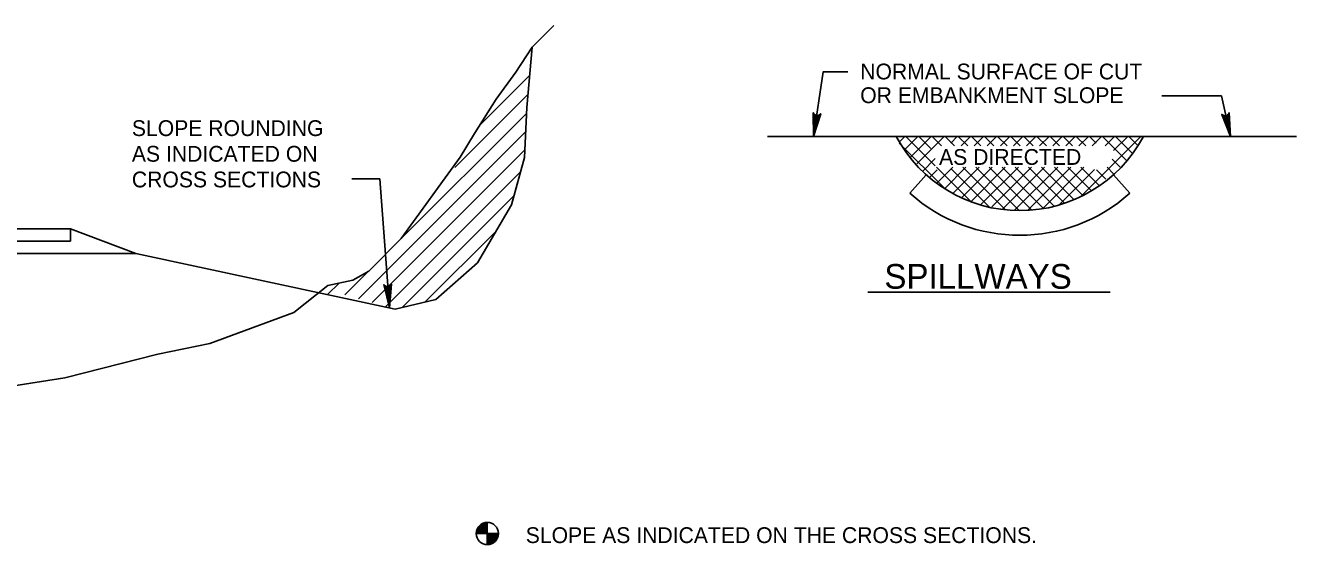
# Model space of a CAD drawing. Extents: x 240 to 1147, y 662 to 1256.
# Drawn here: x 597 to 854.2, y 813.5 to 918.6 of the extents above; entities that cross this region are included whole.
import ezdxf

# ---------------------------------------------------------------- set-up
doc = ezdxf.new("R2010")
doc.units = 0
for name, color, linetype in [('1', 7, 'Continuous'), ('2', 7, 'Continuous'), ('3', 7, 'Continuous')]:
    doc.layers.add(name, color=color, linetype=linetype)

msp = doc.modelspace()

# ---------------------------------------------------------------- linework, layer by layer
at = {"layer": '1'}
for points in [[(757.676, 900.521125), (757.326, 900.402375), (756.44075, 896.112875), (757.676, 900.521125), (757.90725, 900.721125), (756.44075, 896.112875), (756.872, 900.464875), (756.574, 900.671125), (756.44075, 896.112875), (756.397, 900.946125), (756.574, 900.671125)], [(840.36975, 900.666875), (840.0885, 900.429375), (840.822, 896.112875), (840.36975, 900.666875), (840.5135, 900.939875), (840.822, 896.112875), (839.64275, 900.325375), (839.29075, 900.408625), (840.822, 896.112875), (839.024, 900.600375), (839.29075, 900.408625)], [(670.88625, 865.995875), (670.5695, 865.802125), (670.655, 861.424875), (670.88625, 865.995875), (671.0675, 866.243625), (670.655, 861.424875), (670.11325, 865.764625), (669.77775, 865.899875), (670.655, 861.424875), (669.5425, 866.129125), (669.77775, 865.899875)]]:
    msp.add_lwpolyline(points, dxfattribs=at)
at = {"layer": '2'}
for p, q in [((688.9945, 898.485375), (699.05275, 908.543625)), ((683.88, 889.835375), (698.7195, 904.674875)), ((826.914, 904.372125), (838.94275, 904.372125)), ((838.94275, 904.372125), (840.822, 896.112875)), ((672.655, 875.074875), (698.43, 900.849875)), ((664.3715, 863.256125), (698.23625, 897.120875)), ((747.1615, 896.112875), (854.1615, 896.112875)), ((773.1845, 896.112875), (823.1845, 896.112875)), ((773.90325, 895.089875), (774.926, 896.112875)), ((774.92825, 893.464875), (777.57825, 896.112875)), ((781.051, 890.191875), (775.12825, 896.112875)), ((775.99275, 891.877375), (780.22825, 896.112875)), ((777.347, 890.579375), (782.88025, 896.112875)), ((780.176, 893.716375), (777.77825, 896.112875)), ((782.3345, 894.210625), (780.43025, 896.112875)), ((784.9865, 894.210625), (783.08225, 896.112875)), ((784.20275, 894.784625), (785.53225, 896.112875)), ((787.6365, 894.210625), (785.7345, 896.112875)), ((786.28025, 894.210625), (788.1845, 896.112875)), ((790.2885, 894.210625), (788.3845, 896.112875)), ((788.93225, 894.210625), (790.8365, 896.112875)), ((792.94075, 894.210625), (791.0365, 896.112875)), ((791.5845, 894.210625), (793.4885, 896.112875)), ((795.59275, 894.210625), (793.6885, 896.112875)), ((794.2365, 894.210625), (796.1385, 896.112875)), ((798.24475, 894.210625), (796.34075, 896.112875)), ((796.8885, 894.210625), (798.79075, 896.112875)), ((800.89475, 894.210625), (798.99275, 896.112875)), ((799.5385, 894.210625), (801.44275, 896.112875)), ((803.547, 894.210625), (801.64475, 896.112875)), ((802.19075, 894.210625), (804.09475, 896.112875)), ((806.199, 894.210625), (804.29475, 896.112875)), ((804.84275, 894.210625), (806.74475, 896.112875)), ((808.851, 894.210625), (806.947, 896.112875)), ((807.49475, 894.210625), (809.397, 896.112875)), ((811.50325, 894.210625), (809.599, 896.112875)), ((810.14475, 894.210625), (812.049, 896.112875)), ((810.651, 884.108625), (822.65525, 896.112875)), ((813.61375, 894.750125), (812.251, 896.112875)), ((812.797, 894.210625), (814.701, 896.112875)), ((819.66975, 891.346125), (814.901, 896.112875)), ((815.449, 894.210625), (817.35325, 896.112875)), ((817.14625, 893.255875), (820.00325, 896.112875)), ((820.9135, 892.754375), (817.55325, 896.112875)), ((820.15325, 896.164875), (821.90325, 894.414875)), ((822.95525, 896.014875), (822.85725, 896.112875)), ((667.13625, 862.485375), (698.04025, 893.389625)), ((782.9365, 885.654375), (773.801, 894.787875)), ((778.48225, 889.064875), (781.051, 891.631625)), ((788.45725, 882.783625), (781.34275, 889.898125)), ((781.451, 886.727375), (784.61975, 889.898125)), ((782.9865, 885.612875), (787.272, 889.898125)), ((784.66775, 884.641875), (789.924, 889.898125)), ((786.497, 883.819125), (792.576, 889.898125)), ((795.1635, 881.379375), (786.64475, 889.898125)), ((788.17825, 882.850375), (795.22825, 889.898125)), ((797.976, 881.219125), (789.297, 889.898125)), ((790.31975, 882.339875), (797.87825, 889.898125)), ((800.572, 881.275375), (791.949, 889.898125)), ((792.53025, 881.898125), (800.53025, 889.898125)), ((802.98225, 881.516875), (794.601, 889.898125)), ((794.6885, 881.404375), (803.18225, 889.898125)), ((797.176, 881.241875), (805.8345, 889.898125)), ((805.1385, 882.010625), (797.25325, 889.898125)), ((799.80525, 881.219125), (808.4845, 889.898125)), ((807.1865, 882.616875), (799.90325, 889.898125)), ((809.0865, 883.366875), (802.55525, 889.898125)), ((802.874, 881.635625), (811.1365, 889.898125)), ((810.87825, 884.227375), (805.20725, 889.898125)), ((812.526, 885.231625), (807.8595, 889.898125)), ((814.2845, 886.125375), (810.5115, 889.898125)), ((817.14075, 888.571125), (815.8135, 889.898125)), ((818.4595, 889.906625), (816.8615, 891.504625)), ((663.047, 887.517625), (668.70425, 887.517625)), ((668.70425, 887.517625), (670.655, 861.424875)), ((669.90075, 861.712375), (697.1715, 888.985375)), ((775.9135, 884.648125), (779.25325, 888.366875)), ((779.947, 887.877375), (781.44775, 889.376625)), ((792.0595, 881.833625), (784.38125, 889.511625)), ((806.09275, 882.202375), (813.312, 889.421625)), ((815.601, 887.460625), (813.71375, 889.346375)), ((820.45725, 884.648125), (817.11775, 888.366875)), ((673.2175, 861.495875), (695.834, 884.112375)), ((529.92775, 877.420875), (606.16525, 877.420875)), ((619.34025, 872.420875), (606.16525, 877.420875)), ((606.16525, 874.920875), (606.16525, 877.420875)), ((677.83625, 862.579125), (692.23625, 876.979125)), ((515.59025, 874.920875), (606.16525, 874.920875)), ((661.607, 864.027125), (666.3695, 868.789625)), ((658.14875, 864.106125), (660.48825, 866.443625)), ((767.4595, 864.596125), (816.46575, 864.596125)), ((690.464, 813.473375), (690.464, 817.963125)), ((690.464, 813.473375), (690.464, 817.963125)), ((690.464, 817.960875), (690.464, 813.471375)), ((690.464, 817.960875), (690.464, 813.471375)), ((692.70775, 815.719375), (688.21825, 815.719375)), ((692.70775, 815.717125), (688.21825, 815.717125)), ((688.22025, 815.719375), (692.71, 815.719375)), ((688.22025, 815.717125), (692.71, 815.717125))]:
    msp.add_line(p, q, dxfattribs=at)
for points in [[(309.96525, 917.420875), (317.46525, 908.670875), (322.46525, 902.420875), (338.71525, 864.920875), (348.71525, 864.920875), (369.96525, 868.670875), (473.71525, 873.045875), (490.59025, 871.795875), (515.59025, 872.420875), (619.34025, 872.420875), (671.84025, 861.170875), (680.06125, 863.102125), (688.48625, 870.558375), (695.33, 882.272875), (697.96125, 891.858375), (698.48825, 901.977125), (699.54025, 914.227125), (703.88625, 918.620875)], [(593.409, 845.443625), (604.9925, 847.274875), (623.81525, 852.033375), (634.31125, 854.231125), (651.32375, 860.456125), (658.20075, 865.947875), (663.2695, 867.045875), (666.52575, 868.877125), (673.0425, 875.468625), (684.98625, 891.945875), (687.882, 896.706125), (692.22575, 903.662375), (696.207, 909.154125), (699.54025, 914.227125)], [(763.401, 909.231625), (758.401, 909.231625), (756.44075, 896.112875)], [(690.45575, 817.842125), (690.16825, 817.825625), (689.9015, 817.756875), (689.65375, 817.677625), (689.3975, 817.552625), (689.15375, 817.398375), (688.9265, 817.206875), (688.7515, 816.990125), (688.5765, 816.723375), (688.46, 816.458875), (688.36825, 816.169375), (688.32875, 815.908875), (688.3245, 815.710875)], [(690.45775, 817.683875), (690.19325, 817.667125), (689.94525, 817.604625), (689.712, 817.529625), (689.4765, 817.415125), (689.2495, 817.269375), (689.04125, 817.094375), (688.88075, 816.896375), (688.71625, 816.646375), (688.61, 816.402625), (688.5245, 816.131875), (688.487, 815.894375), (688.48275, 815.710875)], [(690.45775, 817.523375), (690.21825, 817.508875), (689.989, 817.450625), (689.7725, 817.379625), (689.55375, 817.275625), (689.34325, 817.140125), (689.15575, 816.981875), (689.01, 816.802625), (688.85775, 816.571375), (688.76, 816.346375), (688.68075, 816.096375), (688.6475, 815.881875), (688.64325, 815.710875)], [(690.45775, 817.363125), (690.24325, 817.350625), (690.03275, 817.296375), (689.83275, 817.231875), (689.63275, 817.135875), (689.439, 817.010875), (689.27025, 816.869375), (689.137, 816.706875), (688.9975, 816.494375), (688.90775, 816.292125), (688.835, 816.058875), (688.80575, 815.867125), (688.8015, 815.710875)], [(690.45775, 817.204625), (690.26825, 817.192125), (690.07875, 817.144375), (689.89125, 817.083875), (689.71, 816.996375), (689.53275, 816.883875), (689.38275, 816.756875), (689.26625, 816.613125), (689.139, 816.417125), (689.05775, 816.233875), (688.99125, 816.023375), (688.96625, 815.852625), (688.962, 815.710875)], [(690.45775, 817.044375), (690.29325, 817.033875), (690.1225, 816.990125), (689.9515, 816.935875), (689.789, 816.856875), (689.62875, 816.754625), (689.4975, 816.644375), (689.39525, 816.519375), (689.27875, 816.340125), (689.20775, 816.177625), (689.1475, 815.985875), (689.1245, 815.840125), (689.12025, 815.710875)], [(690.45775, 816.883875), (690.31825, 816.875625), (690.16625, 816.838125), (690.01, 816.788125), (689.86625, 816.717125), (689.7225, 816.625625), (689.612, 816.531875), (689.5245, 816.425625), (689.42025, 816.265125), (689.35575, 816.123375), (689.30375, 815.950625), (689.28275, 815.825625), (689.28075, 815.710875)], [(690.45775, 816.725625), (690.34125, 816.717125), (690.21, 816.683875), (690.07025, 816.638125), (689.94325, 816.577625), (689.81825, 816.496375), (689.7265, 816.419375), (689.65375, 816.329625), (689.56, 816.188125), (689.50575, 816.067125), (689.45775, 815.915125), (689.44325, 815.810875), (689.44125, 815.710875)], [(690.45775, 816.565125), (690.36625, 816.558875), (690.25375, 816.529625), (690.13075, 816.490125), (690.0225, 816.438125), (689.912, 816.367125), (689.84125, 816.308875), (689.78075, 816.235875), (689.6995, 816.113125), (689.65575, 816.010875), (689.614, 815.877625), (689.6015, 815.796375), (689.5995, 815.710875)], [(690.45775, 816.404625), (690.39125, 816.400625), (690.2995, 816.377625), (690.189, 816.342125), (690.0995, 816.298375), (690.00575, 816.240125), (689.95575, 816.196375), (689.91, 816.142125), (689.84125, 816.035875), (689.80575, 815.954625), (689.77025, 815.842125), (689.762, 815.783875), (689.76, 815.710875)], [(690.45775, 816.246375), (690.41625, 816.242125), (690.34325, 816.223375), (690.2495, 816.194375), (690.17875, 816.158875), (690.1015, 816.110875), (690.06825, 816.083875), (690.039, 816.046375), (689.98075, 815.958875), (689.95575, 815.898375), (689.9265, 815.804625), (689.92025, 815.769375), (689.91825, 815.710875)], [(690.087, 815.717125), (690.089, 815.733875), (690.10375, 815.785875), (690.12875, 815.865125), (690.15375, 815.917125), (690.19125, 815.977625), (690.20375, 815.990125), (690.22025, 816.004625), (690.29125, 816.052625), (690.33275, 816.069375), (690.40375, 816.092125), (690.41825, 816.094375), (690.464, 816.096375)], [(690.45775, 815.923375), (690.43075, 815.917125), (690.36825, 815.896375), (690.33275, 815.879625), (690.29525, 815.856875), (690.262, 815.806875), (690.25375, 815.785875), (690.239, 815.735875), (690.237, 815.710875)], [(690.42025, 815.708875), (690.42025, 815.740125), (690.4245, 815.756875), (690.4245, 815.758875), (690.43275, 815.769375), (690.43275, 815.769375), (690.4495, 815.779625), (690.4495, 815.779625)], [(690.84125, 815.719375), (690.839, 815.702625), (690.8265, 815.648375), (690.8015, 815.569375), (690.7745, 815.517125), (690.737, 815.456875), (690.7265, 815.444375), (690.70775, 815.429625), (690.637, 815.383875), (690.5975, 815.365125), (690.5245, 815.342125), (690.51, 815.340125), (690.464, 815.340125)], [(690.4725, 813.592125), (690.76, 813.610875), (691.02875, 813.677625), (691.2745, 813.758875), (691.53075, 813.881875), (691.7745, 814.038125), (692.0015, 814.229625), (692.1765, 814.444375), (692.35375, 814.713125), (692.46825, 814.975625), (692.56, 815.267125), (692.5995, 815.525625), (692.60575, 815.725625)], [(690.4725, 813.752625), (690.735, 813.769375), (690.98275, 813.831875), (691.21625, 813.906875), (691.4515, 814.021375), (691.67875, 814.165125), (691.887, 814.342125), (692.0475, 814.540125), (692.212, 814.788125), (692.32025, 815.031875), (692.40375, 815.302625), (692.44125, 815.540125), (692.44525, 815.725625)], [(690.4725, 813.910875), (690.71, 813.927625), (690.939, 813.985875), (691.15575, 814.054625), (691.3745, 814.160875), (691.585, 814.294375), (691.7745, 814.454625), (691.92025, 814.633875), (692.0725, 814.865125), (692.17025, 815.088125), (692.2495, 815.340125), (692.28275, 815.554625), (692.285, 815.725625)], [(690.4725, 814.071375), (690.687, 814.083875), (690.89525, 814.138125), (691.0975, 814.202625), (691.2975, 814.300625), (691.489, 814.423375), (691.66, 814.565125), (691.79125, 814.727625), (691.93075, 814.942125), (692.02025, 815.144375), (692.09325, 815.375625), (692.1225, 815.569375), (692.1265, 815.725625)], [(690.4725, 814.231875), (690.662, 814.244375), (690.8515, 814.292125), (691.037, 814.350625), (691.21825, 814.440125), (691.39525, 814.552625), (691.54525, 814.677625), (691.662, 814.821375), (691.79125, 815.017125), (691.87025, 815.200625), (691.937, 815.413125), (691.964, 815.581875), (691.96625, 815.725625)], [(690.4725, 814.390125), (690.637, 814.400625), (690.80775, 814.444375), (690.97875, 814.500625), (691.14125, 814.579625), (691.3015, 814.681875), (691.43075, 814.790125), (691.53275, 814.917125), (691.6495, 815.094375), (691.72025, 815.256875), (691.78075, 815.448375), (691.80375, 815.596375), (691.80775, 815.725625)], [(690.4725, 814.550625), (690.612, 814.558875), (690.762, 814.598375), (690.91825, 814.648375), (691.062, 814.719375), (691.20575, 814.808875), (691.31625, 814.902625), (691.40375, 815.010875), (691.51, 815.171375), (691.5725, 815.313125), (691.6265, 815.483875), (691.64525, 815.610875), (691.6475, 815.725625)], [(690.4725, 814.710875), (690.587, 814.717125), (690.71825, 814.750625), (690.85775, 814.796375), (690.985, 814.856875), (691.112, 814.938125), (691.2015, 815.015125), (691.2765, 815.104625), (691.36825, 815.246375), (691.4225, 815.369375), (691.47025, 815.521375), (691.487, 815.623375), (691.489, 815.725625)], [(690.4725, 814.871375), (690.562, 814.875625), (690.6745, 814.904625), (690.7995, 814.944375), (690.90775, 814.996375), (691.01625, 815.067125), (691.089, 815.127625), (691.1475, 815.198375), (691.22875, 815.323375), (691.2725, 815.425625), (691.314, 815.556875), (691.3265, 815.638125), (691.32875, 815.725625)], [(690.4725, 815.029625), (690.537, 815.033875), (690.63075, 815.058875), (690.739, 815.092125), (690.82875, 815.135875), (690.9225, 815.196375), (690.9745, 815.240125), (691.01825, 815.294375), (691.087, 815.398375), (691.1245, 815.481875), (691.15775, 815.594375), (691.16825, 815.652625), (691.17025, 815.725625)], [(690.4725, 815.190125), (690.512, 815.192125), (690.587, 815.210875), (690.68075, 815.242125), (690.7515, 815.275625), (690.8265, 815.325625), (690.86, 815.352625), (690.889, 815.388125), (690.9475, 815.475625), (690.9745, 815.538125), (691.00375, 815.629625), (691.00775, 815.667125), (691.01, 815.725625)], [(690.4725, 815.510875), (690.4975, 815.517125), (690.562, 815.538125), (690.59525, 815.554625), (690.63275, 815.579625), (690.66625, 815.627625), (690.6745, 815.650625), (690.69125, 815.698375), (690.69125, 815.725625)], [(690.51, 815.725625), (690.50775, 815.694375), (690.50575, 815.677625), (690.50375, 815.675625), (690.49525, 815.667125), (690.49525, 815.667125), (690.47875, 815.654625), (690.47875, 815.654625)]]:
    msp.add_lwpolyline(points, dxfattribs=at)
for centre in [(690.463595, 815.71848), (690.463595, 815.716886), (690.465254, 815.71848), (690.465254, 815.716886)]:
    msp.add_circle(centre, 2.24484, dxfattribs=at)
for radius, start, end in [(28.333333, 208.07248611, 331.92751111), (33.333333, 228.07296389, 311.92703056)]:
    msp.add_arc((798.185333, 909.447125), radius, start, end, dxfattribs=at)

# ---------------------------------------------------------------- texts
at = {"layer": '3'}
for s, height, p in [('NORMAL SURFACE OF CUT', 3.1999875, (765.89275, 907.681625)), ('OR EMBANKMENT SLOPE', 3.1999875, (765.89275, 902.881625)), ('SLOPE ROUNDING', 3.1999875, (618.559, 896.212625)), ('AS INDICATED ON', 3.1999875, (618.559, 891.014875)), ('AS DIRECTED', 3.1999875, (781.84075, 890.375375)), ('CROSS SECTIONS', 3.1999875, (618.559, 885.817125)), ('SPILLWAYS', 4.9998615, (770.78225, 865.294125)), ('SLOPE AS INDICATED ON THE CROSS SECTIONS.', 3.1999875, (698.23075, 813.783875))]:
    msp.add_text(s, height=height, dxfattribs=at).set_placement(p)

doc.saveas('drawing.dxf')
